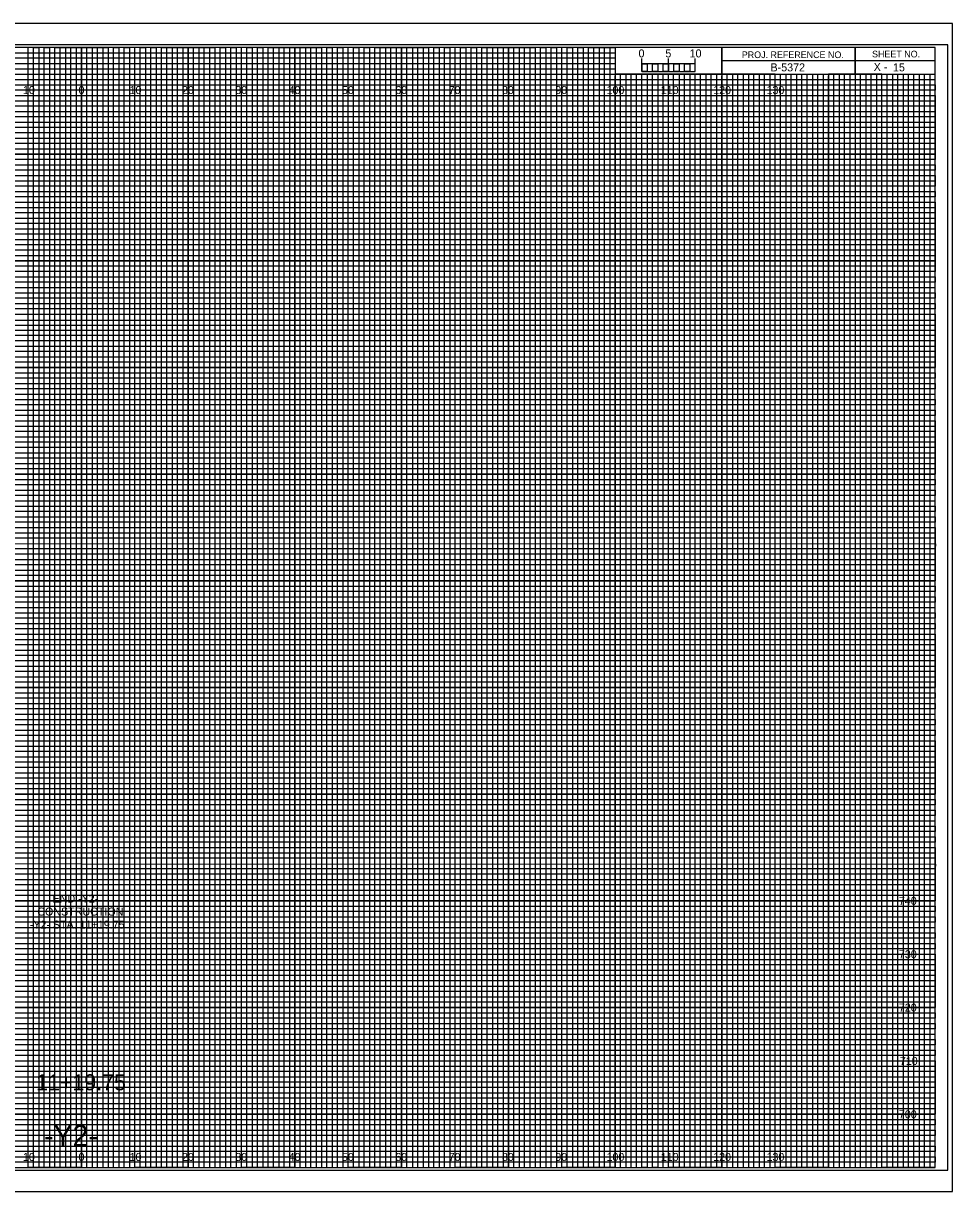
# Model space of a CAD drawing. Extents: x -13 to 323, y -5 to 534.
# Drawn here: x 149.1 to 323.3, y 315.5 to 534.5 of the extents above; entities that cross this region are included whole.
import ezdxf

# ---------------------------------------------------------------- set-up
doc = ezdxf.new("R2010")
doc.units = 0
for name, color, linetype in [('Exist XS Center Line Elevation Label', 7, 'Continuous'), ('Prop XS Alignment Label', 7, 'Continuous'), ('Prop XS Bar Scale Labels', 7, 'Continuous'), ('Prop XS Elevation Labels', 7, 'Continuous'), ('Prop XS Offset Labels', 7, 'Continuous'), ('Prop XS Project Number', 7, 'Continuous'), ('Prop XS Sheet Number', 7, 'Continuous'), ('Prop XS Station Labels', 7, 'Continuous'), ('Sheet Cross Section CELL', 7, 'Continuous'), ('Sheet Cross Section Grid Major CELL', 7, 'Continuous'), ('Sheet Cross Section Grid Middle CELL', 7, 'Continuous'), ('Sheet Cross Section Grid Minor 1 CELL', 7, 'Continuous'), ('Sheet Cross Section Grid Minor 2 CELL', 7, 'Continuous'), ('Sheet Cross Section Scale CELL', 7, 'Continuous'), ('Sheet Cutting Line CELL', 7, 'Continuous'), ('Sheet DOT Grid CELL', 7, 'Continuous'), ('Sheet Plot Border Inside CELL', 7, 'Continuous'), ('Sheet Plot Border Outside CELL', 7, 'Continuous')]:
    doc.layers.add(name, color=color, linetype=linetype)

msp = doc.modelspace()

# ---------------------------------------------------------------- linework, layer by layer
at = {"layer": 'Sheet Cross Section CELL'}
for p, q in [((305, 530), (305, 525)), ((305, 525), (305, 530)), ((280, 527.5), (280, 525)), ((320, 527.49), (280, 527.49)), ((280, 525), (320, 525))]:
    msp.add_line(p, q, dxfattribs=at)
for points in [[(320, 530), (0, 530), (0, 320), (320, 320)], [(280, 530), (260, 530), (260, 525.03), (280, 525.03)], [(320, 530), (280, 530), (280, 525), (320, 525)]]:
    msp.add_lwpolyline(points, close=True, dxfattribs=at)
at = {"layer": 'Sheet Cross Section Grid Major CELL'}
for p, q in [((150, 530), (140, 530)), ((150, 320), (150, 530)), ((170, 530), (160, 530)), ((160, 530), (160, 320)), ((170, 320), (170, 530)), ((190, 530), (180, 530)), ((180, 530), (180, 320)), ((190, 320), (190, 530)), ((210, 530), (200, 530)), ((200, 530), (200, 320)), ((210, 320), (210, 530)), ((230, 530), (220, 530)), ((220, 530), (220, 320)), ((230, 320), (230, 530)), ((250, 530), (240, 530)), ((240, 530), (240, 320)), ((250, 320), (250, 530)), ((260, 530), (260, 320)), ((270, 320), (270, 525)), ((290, 525), (280, 525)), ((280, 525), (280, 320)), ((290, 320), (290, 525)), ((310, 525), (300, 525)), ((300, 525), (300, 320)), ((310, 320), (310, 525)), ((160, 320), (150, 320)), ((180, 320), (170, 320)), ((200, 320), (190, 320)), ((220, 320), (210, 320)), ((240, 320), (230, 320)), ((260, 320), (250, 320)), ((280, 320), (270, 320)), ((300, 320), (290, 320)), ((320, 320), (310, 320)), ((320, 320), (320, 320))]:
    msp.add_line(p, q, dxfattribs=at)
for points in [[(0, 520), (320, 520), (320, 510), (0, 510)], [(0, 500), (320, 500), (320, 490), (0, 490)], [(0, 480), (320, 480), (320, 470), (0, 470)], [(0, 460), (320, 460), (320, 450), (0, 450)], [(0, 440), (320, 440), (320, 430), (0, 430)], [(0, 420), (320, 420), (320, 410), (0, 410)], [(0, 400), (320, 400), (320, 390), (0, 390)], [(0, 380), (320, 380), (320, 370), (0, 370)], [(0, 360), (320, 360), (320, 350), (0, 350)], [(0, 340), (320, 340), (320, 330), (0, 330)]]:
    msp.add_lwpolyline(points, dxfattribs=at)
at = {"layer": 'Sheet Cross Section Grid Middle CELL'}
for points in [[(145, 320), (155, 320), (155, 530), (165, 530), (165, 320), (175, 320), (175, 530), (185, 530), (185, 320), (195, 320), (195, 530), (205, 530), (205, 320), (215, 320), (215, 530), (225, 530), (225, 320), (235, 320), (235, 530), (245, 530), (245, 320), (255, 320), (255, 530), (259.93, 530), (260, 530), (260, 525), (264.99, 525), (264.99, 320), (275, 320), (275, 525), (285, 525), (285, 320), (295, 320), (295, 525), (305, 525), (305, 320), (315, 320), (315, 525)], [(0, 525), (275, 525)], [(0, 505), (320, 505), (320, 515), (0, 515)], [(0, 485), (320, 485), (320, 495), (0, 495)], [(0, 465), (320, 465), (320, 475), (0, 475)], [(0, 445), (320, 445), (320, 455), (0, 455)], [(0, 425), (320, 425), (320, 435), (0, 435)], [(0, 405), (320, 405), (320, 415), (0, 415)], [(0, 385), (320, 385), (320, 395), (0, 395)], [(0, 365), (320, 365), (320, 375), (0, 375)], [(0, 345), (320, 345), (320, 355), (0, 355)], [(0, 325), (320, 325), (320, 335), (0, 335)]]:
    msp.add_lwpolyline(points, dxfattribs=at)
at = {"layer": 'Sheet Cross Section Grid Minor 1 CELL'}
for p, q in [((0, 529), (260, 529)), ((260, 527.98), (0, 527.98)), ((260, 529), (260, 527.98)), ((0, 527), (260, 527)), ((260, 525.89), (0, 525.89)), ((260, 527), (260, 525.89)), ((0, 524), (320, 524))]:
    msp.add_line(p, q, dxfattribs=at)
for points in [[(0, 523), (270, 523), (320, 523), (320, 522), (0, 522)], [(0, 521), (320, 521), (320, 519), (0, 519)], [(0, 518), (320, 518), (320, 517), (0, 516.98)], [(0, 516), (320, 516), (320, 514), (0, 514)], [(0, 513), (320, 513), (320, 512), (0, 512)], [(0, 511), (320, 511), (320, 509), (0, 509)], [(0, 508), (320, 508), (320, 507), (0, 507)], [(0, 506), (320, 506), (320, 504), (0, 504)], [(0, 503), (320, 503), (320, 502), (0, 502)], [(0, 501), (320, 501), (320, 499), (0, 499)], [(0, 498), (320, 498), (320, 497), (0, 497)], [(0, 496), (320, 496), (320, 493.95), (320, 493), (320, 492), (0, 492)], [(0, 494), (320, 494), (320, 493), (0, 493)], [(0, 491), (320, 491), (320, 489), (0, 489.03)], [(0, 489.03), (320, 489), (320, 488), (0, 488)], [(0, 487), (320, 487), (320, 486), (0, 486)], [(0, 484), (320, 484), (320, 483), (0, 483)], [(0, 482), (320, 482), (320, 481), (0, 481)], [(-0.07, 478.89), (320, 478.89), (320, 477.88), (-0.07, 477.88)], [(0, 477), (320, 477), (320, 476), (0, 476)], [(0, 474), (320, 474), (320, 473), (0, 473)], [(0, 472), (320, 472), (320, 471), (0, 471)], [(0, 469), (320, 469), (320, 468), (0, 468)], [(0, 467), (320, 467), (320, 466), (0, 466)], [(0, 464), (320, 464), (320, 463), (0, 463)], [(0, 462), (320, 462), (320, 461), (0, 461)], [(0, 459), (320, 459), (319.99, 457.98), (0, 458)], [(0, 457), (320, 457), (320, 456), (0, 456)], [(0, 454), (320, 454), (320, 453), (0, 453)], [(0, 452), (320, 452), (320, 451), (0, 451)], [(0, 449), (320, 449), (320, 448), (0, 448)], [(0, 447), (320, 447), (320, 446), (0, 446)], [(0, 444), (320, 444), (320, 443), (0, 443)], [(0, 442), (320, 442), (320, 441), (0, 441)], [(0, 439), (320, 439), (320, 438), (0, 438)], [(0, 436.99), (320.07, 436.91), (320, 436), (0, 436)], [(0, 434), (320, 434), (320, 433), (0, 433)], [(0, 432), (320, 432), (320, 431), (0, 431)], [(0, 429), (320, 429), (320, 428), (0, 428)], [(0, 427), (320, 427), (320, 426), (0, 426)], [(0, 424), (320, 424), (320, 423), (0, 423)], [(0, 422), (320, 422), (320, 421), (0, 421)], [(0, 419), (320, 419), (320, 418), (0, 418)], [(0, 417), (320, 417), (320, 416), (0, 416)], [(0, 414), (320, 414), (320, 413), (0, 413)], [(0, 412), (320, 412), (320, 411), (0, 411)], [(0, 409), (320, 409), (320, 408), (0, 408)], [(0, 407), (320, 407), (320, 406), (0, 406)], [(0, 404), (320, 404), (320, 403), (0, 403)], [(0, 402), (320, 402), (320, 401), (0, 401)], [(0, 399), (320, 399), (319.99, 397.98), (0, 398)], [(0, 397), (320, 397), (320, 396), (0, 396)], [(0, 394), (320, 394), (320, 393), (0, 393)], [(0, 392), (320, 392), (320, 391), (0, 391)], [(0, 389), (320, 389), (320, 388), (0, 388)], [(0, 387), (320, 387), (320, 386), (0, 386)], [(0, 384), (320, 384), (320, 383), (0, 383)], [(0, 382), (320, 382), (320, 381), (0, 381)], [(0, 379), (320, 379), (320, 378), (0, 378)], [(0, 376.99), (320.07, 376.91), (320, 376), (0, 376)], [(0, 374), (320, 374), (320, 373), (0, 373)], [(0, 372), (320, 372), (320, 371), (0, 371)], [(0, 369), (320, 369), (320, 368), (0, 368)], [(0, 367), (320, 367), (320, 366), (0, 366)], [(0, 364), (320, 364), (320, 363), (0, 363)], [(0, 362), (320, 362), (320, 361), (0, 361)], [(0, 359), (320, 359), (320, 358), (0, 358)], [(0, 357), (320, 357), (320, 356), (0, 356)], [(0, 354), (320, 354), (320, 353), (0, 353)], [(0, 352), (320, 352), (320, 351), (0, 351)], [(0, 349), (320, 349), (320, 348), (0, 348)], [(0, 347), (320, 347), (320, 346), (0, 346)], [(0, 344), (320, 344), (320, 343), (0, 343)], [(0, 342), (320, 342), (320, 341), (0, 341)], [(0, 339), (320, 339), (320, 338), (0, 338)], [(0, 337), (320, 337), (320, 336), (0, 336)], [(0, 334), (320, 334), (320, 333), (0, 333)], [(0, 332), (320, 332), (320, 331), (0, 331)], [(0, 329), (320, 329), (320, 328), (0, 328)], [(0, 327), (320, 327), (320, 326), (0, 326)], [(0, 324), (320, 324), (320, 323), (0, 323)], [(0, 322), (320, 322), (320, 321), (0, 321)]]:
    msp.add_lwpolyline(points, dxfattribs=at)
at = {"layer": 'Sheet Cross Section Grid Minor 2 CELL'}
for p, q in [((267, 525), (266.01, 525)), ((266.01, 525), (266.01, 320)), ((267, 320), (267, 525)), ((269, 525), (268, 525)), ((268, 525), (268, 320)), ((269, 320), (269, 525)), ((266.01, 320), (265, 320)), ((268, 320), (267, 320))]:
    msp.add_line(p, q, dxfattribs=at)
for points in [[(150, 320), (151, 320), (151, 530), (152, 530), (152, 320)], [(152, 320), (153, 320), (153, 530), (154, 530), (154, 320)], [(155, 320), (156, 320), (156, 530), (157, 530), (157, 320)], [(157, 320), (158, 320), (158, 530), (159, 530), (159, 320)], [(160, 320), (161, 320), (161, 530), (162, 530), (162, 320)], [(162, 320), (163, 320), (163, 530), (164, 530), (164, 320)], [(165, 320), (166, 320), (166, 530), (167, 530), (167, 320)], [(167, 320), (168, 320), (168, 530), (169, 530), (169, 320)], [(170, 320), (171, 320), (171, 530), (172, 530), (172, 320)], [(172, 320), (173, 320), (173, 530), (174, 530), (174, 320)], [(175, 320), (176, 320), (176, 530), (177, 530), (177, 320)], [(177, 320), (178, 320), (178, 530), (179, 530), (179, 320)], [(180, 320), (181, 320), (181, 530), (182, 530), (182, 320)], [(182, 320), (183, 320), (183, 530), (184, 530), (184, 320)], [(185, 320), (186, 320), (186, 530), (187, 530), (187, 320)], [(187, 320), (188, 320), (188, 530), (189, 530), (189, 320)], [(190, 320), (191, 320), (191, 530), (192, 530), (192, 320)], [(192, 320), (193, 320), (193, 530), (194, 530), (194, 320)], [(195, 320), (196, 320), (196, 530), (197, 530), (197, 320)], [(197, 320), (198, 320), (198, 530), (199, 530), (199, 320)], [(200, 320), (201, 320), (201, 530), (202, 530), (202, 320)], [(202, 320), (203, 320), (203, 530), (204, 530), (204, 320)], [(205, 320), (206, 320), (206, 530), (207, 530), (207, 320)], [(207, 320), (208, 320), (208, 530), (209, 530), (209, 320)], [(210, 320), (211, 320), (211, 530), (212, 530), (212, 320)], [(212, 320), (213, 320), (213, 530), (214, 530), (214, 320)], [(215, 320), (216, 320), (216, 530), (217, 530), (217, 320)], [(217, 320), (218, 320), (218, 530), (219, 530), (219, 320)], [(220, 320), (221, 320), (221, 530), (222, 530), (222, 320)], [(222, 320), (223, 320), (223, 530), (224, 530), (224, 320)], [(225, 320), (226, 320), (226, 530), (227, 530), (227, 320)], [(227, 320), (228, 320), (228, 530), (229, 530), (229, 320)], [(230, 320), (231, 320), (231, 530), (232, 530), (232, 320)], [(232, 320), (233, 320), (233, 530), (234, 530), (234, 320)], [(235, 320), (236, 320), (236, 530), (237, 530), (237, 320)], [(237, 320), (238, 320), (238, 530), (239, 530), (239, 320)], [(240, 320), (241, 320), (241, 530), (242, 530), (242, 320)], [(242, 320), (243, 320), (243, 530), (244, 530), (244, 320)], [(245, 320), (246, 320), (246, 530), (247, 530), (247, 320)], [(247, 320), (248, 320), (248, 530), (249, 530), (249, 320)], [(250, 320), (251, 320), (251, 530), (252, 530), (252, 320)], [(252, 320), (253, 320), (253, 530), (254, 530), (254, 320)], [(255, 320), (256, 320), (256, 530), (257, 530), (257, 320)], [(257, 320), (258, 320), (258, 530), (259, 530), (259, 320)], [(260, 320), (261, 320), (261, 525), (262.02, 525), (262.02, 320)], [(262, 320), (263, 320), (263, 525), (263.99, 525), (263.99, 320)], [(270, 320), (270.98, 320), (270.98, 525), (272, 525), (272, 320)], [(272, 320), (273, 320), (273, 525), (274.05, 525), (274.05, 320)], [(275, 320), (276, 320), (276, 525), (277, 525), (277, 320)], [(277, 320), (278, 320), (278, 525), (279, 525), (279, 320)], [(280, 320), (281, 320), (281, 525), (282, 525), (282, 320)], [(282, 320), (283, 320), (283, 525), (284, 525), (284, 320)], [(285, 320), (286, 320), (286, 525), (287, 525), (287, 320)], [(287, 320), (288, 320), (288, 525), (289, 525), (289, 320)], [(290, 320), (291, 320), (291, 525), (292, 525), (292, 320)], [(292, 320), (293, 320), (293, 525), (294, 525), (294, 320)], [(295, 320), (296, 320), (296, 525), (297, 525), (297, 320)], [(297, 320), (298, 320), (298, 525), (299, 525), (299, 320)], [(300, 320), (301, 320), (301, 525), (302, 525), (302, 320)], [(302, 320), (303, 320), (303, 525), (304, 525), (304, 320)], [(305, 320), (306, 320), (306, 525), (307, 525), (307, 320)], [(307, 320), (308, 320), (308, 525), (309, 525), (309, 320)], [(310, 320), (311, 320), (311, 525), (312, 525), (312, 320)], [(312, 320), (313, 320), (313, 525), (314, 525), (314, 320)], [(315, 320), (316, 320), (316, 525), (317, 525), (317, 320)], [(317, 320), (318, 320), (318, 525), (319, 525), (319, 320)]]:
    msp.add_lwpolyline(points, dxfattribs=at)
at = {"layer": 'Sheet Cross Section Scale CELL'}
for p, q in [((265, 525.49), (265, 527.9)), ((265, 526.9), (265, 527.9)), ((270, 525.49), (270, 527.9)), ((275, 525.49), (275, 527.9)), ((275, 526.9), (275, 527.9))]:
    msp.add_line(p, q, dxfattribs=at)
for points in [[(275, 526.9), (265, 526.9), (265, 525.49), (275, 525.49)], [(265, 526.9), (266, 526.9), (266, 525.49), (265, 525.49)], [(267, 526.9), (268, 526.9), (268, 525.49), (267, 525.49)], [(269, 526.9), (270, 526.9), (270, 525.49), (269, 525.49)], [(271, 526.9), (272, 526.9), (272, 525.49), (271, 525.49)], [(273, 526.9), (274, 526.9), (274, 525.49), (273, 525.49)]]:
    msp.add_lwpolyline(points, close=True, dxfattribs=at)
at = {"layer": 'Sheet Cutting Line CELL'}
for p, q in [((323.3, 534.5), (-13.4, 534.5)), ((-13.4, 315.5), (323.3, 315.5))]:
    msp.add_line(p, q, dxfattribs=at)
at = {"layer": 'Sheet DOT Grid CELL'}
for p, q in [((150, 320), (150, 530)), ((160, 320), (160, 530)), ((170, 320), (170, 530)), ((180, 320), (180, 530)), ((190, 320), (190, 530)), ((200, 320), (200, 530)), ((210, 320), (210, 530)), ((220, 320), (220, 530)), ((230, 320), (230, 530)), ((240, 320), (240, 530)), ((250, 320), (250, 530)), ((260, 320), (260, 524.69)), ((270, 320), (270, 524.69)), ((280, 320), (280, 524.69)), ((290, 320), (290, 524.69)), ((300, 320), (300, 524.69)), ((310, 320), (310, 524.69)), ((0, 520), (320, 520)), ((0, 510), (320, 510)), ((0, 500), (320, 500)), ((0, 490), (320, 490)), ((0, 480), (320, 480)), ((0, 470), (320, 470)), ((0, 460), (320, 460)), ((0, 450), (320, 450)), ((0, 440), (320, 440)), ((0, 430), (320, 430)), ((0, 420), (320, 420)), ((0, 410), (320, 410)), ((0, 400), (320, 400)), ((0, 390), (320, 390)), ((0, 380), (320, 380)), ((0, 370), (320, 370)), ((0, 360), (320, 360)), ((0, 350), (320, 350)), ((0, 340), (320, 340)), ((0, 330), (320, 330))]:
    msp.add_line(p, q, dxfattribs=at)
at = {"layer": 'Sheet Plot Border Inside CELL'}
msp.add_lwpolyline([(-10.8, 319.5), (322.4, 319.5), (322.4, 530.5), (-10.8, 530.5)], close=True, dxfattribs=at)
at = {"layer": 'Sheet Plot Border Outside CELL'}
msp.add_lwpolyline([(-13.4, 315.5), (323.3, 315.5), (323.3, 534.5), (-13.4, 534.5)], close=True, dxfattribs=at)

# ---------------------------------------------------------------- texts
at = {"layer": 'Exist XS Center Line Elevation Label'}
for s, p in [('END -Y2- ', (154.55, 369.69)), ('CONSTRUCTION ', (151.68, 367.25)), ('-Y2- STA. 11+19.75', (150.27, 364.81))]:
    msp.add_text(s, height=1.5, rotation=360, dxfattribs=at).set_placement(p)
at = {"layer": 'Prop XS Alignment Label'}
msp.add_text('-Y2-', height=4, dxfattribs=at).set_placement((152.94, 324))
at = {"layer": 'Prop XS Bar Scale Labels'}
for s, p in [('5', (269.44, 528.12)), ('10', (273.99, 528.12))]:
    msp.add_text(s, height=1.5, dxfattribs=at).set_placement(p)
at = {"layer": 'Prop XS Elevation Labels'}
for s, p in [('740', (313.22, 369.25)), ('730', (313.22, 359.25)), ('720', (313.22, 349.25)), ('710', (313.4, 339.25)), ('700', (313.22, 329.25))]:
    msp.add_text(s, height=1.5, dxfattribs=at).set_placement(p)
at = {"layer": 'Prop XS Offset Labels'}
for s, p in [('10', (148.99, 521.25)), ('0', (159.41, 521.25)), ('10', (168.99, 521.25)), ('20', (178.81, 521.25)), ('30', (188.81, 521.25)), ('40', (198.81, 521.25)), ('50', (208.81, 521.25)), ('60', (218.81, 521.25)), ('70', (228.81, 521.25)), ('80', (238.81, 521.25)), ('90', (248.81, 521.25)), ('100', (258.4, 521.25)), ('110', (268.58, 521.25)), ('120', (278.4, 521.25)), ('130', (288.4, 521.25)), ('10', (148.99, 321.25)), ('0', (159.41, 321.25)), ('10', (168.99, 321.25)), ('20', (178.81, 321.25)), ('30', (188.81, 321.25)), ('40', (198.81, 321.25)), ('50', (208.81, 321.25)), ('60', (218.81, 321.25)), ('70', (228.81, 321.25)), ('80', (238.81, 321.25)), ('90', (248.81, 321.25)), ('100', (258.4, 321.25)), ('110', (268.58, 321.25)), ('120', (278.4, 321.25)), ('130', (288.4, 321.25))]:
    msp.add_text(s, height=1.5, dxfattribs=at).set_placement(p)
at = {"layer": 'Prop XS Project Number'}
msp.add_text('B-5372', height=1.5, dxfattribs=at).set_placement((289.15, 525.5))
at = {"layer": 'Prop XS Sheet Number'}
msp.add_text('15', height=1.5, dxfattribs=at).set_placement((312.12, 525.5))
at = {"layer": 'Prop XS Station Labels'}
msp.add_text('11+19.75', height=3, dxfattribs=at).set_placement((151.46, 334.5))
at = {"layer": 'Sheet Cross Section CELL'}
for s, height, p in [('PROJ. REFERENCE NO.', 1.25, (283.77, 527.99)), ('SHEET NO.', 1.25, (308.19, 528.12)), ('X -    ', 1.5, (308.5, 525.58))]:
    msp.add_text(s, height=height, dxfattribs=at).set_placement(p)
at = {"layer": 'Sheet Cross Section Scale CELL'}
msp.add_text('0', height=1.5, dxfattribs=at).set_placement((264.41, 528.12))

doc.saveas('drawing.dxf')
